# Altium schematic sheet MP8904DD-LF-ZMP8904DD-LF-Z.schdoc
size 127 x 101 mm
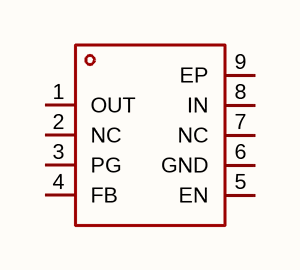
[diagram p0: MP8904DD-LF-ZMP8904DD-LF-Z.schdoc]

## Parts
U?  mp8904dd-lf-z  [DFN-8_L3.0-W2.0-P0.50-BL-EP1.8]  (value not drawn)

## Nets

Not connected (* = marked no-connect by the designer): U? 1(OUT) 2(NC) 3(PG) 4(FB) 5(EN) 6(GND) 7(NC) 8(IN) 9(EP)

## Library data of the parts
U? = mp8904dd-lf-z: 输出极性:正极;工作电压:6.5V;输出电压:500mV~5V;输出电流:500mA;电源纹波抑制比(PSRR):-;输出类型:可调;; Manufacturer: MPS(芯源); AddInBom: yes; ModelId: dcd023d634cb42a999abed934939426d; ModelTransform: 78.74,118.8974,0,0,0,0,0,0,0; Output Configuration: 正极; Voltage - Supply: 6.5V; Output Current: 500mA; Voltage Dropout: 300mV@(500mA); standby current: 100uA; Output Type: 可调; Number of Outputs: 1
